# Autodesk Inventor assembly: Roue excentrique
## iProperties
Author: Flavien MARTY
Shininess: 21.0
PropertySet Name: _Private Model Information
Created: 2001-10
Part Number: Roue excentrique
Document SubType Name: Assemblage
Designer: Flavien MARTY
Control State: 0
Master: False
Checked Out: False
PropertySet Name: Design Tracking Control
Density: 0.0
Volumn: 0.0
Area: 0.0
PropertySet Name: Model Information
